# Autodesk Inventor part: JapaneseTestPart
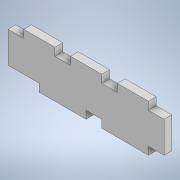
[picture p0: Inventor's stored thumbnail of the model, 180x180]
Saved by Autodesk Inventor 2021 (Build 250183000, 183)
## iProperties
Created: 2026-10
Part Number: JapaneseTestPart
Material: Generic
Document SubType Name: Modeling
Designer: hp
Density: 1 g/cm^3
Appearance: Default
Author: hp
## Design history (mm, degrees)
sketch "Sketch1" dims "d15" = 10
  geometry: L1 (0, 0)-(100, 0); L2 (100, 0)-(100, 20); L3 (100, 20)-(0, 20); L4 (0, 20)-(0, 0); L5 (90, -5)-(90, 0); L6 (90, 0)-(60, 0); L7 (60, 0)-(60, -5); L8 (60, -5)-(90, -5); L9 (50, -5)-(50, 0); L10 (20, 0)-(20, -5); L11 (20, -5)-(50, -5); L12 (50, 0)-(20, 0); L13 (60, 20)-(60, 25); L14 (70, 25)-(70, 20); L15 (70, 20)-(90, 20); L16 (90, 25)-(70, 25); L17 (90, 20)-(90, 25); L18 (30, 20)-(30, 25); L19 (30, 25)-(10, 25); L20 (10, 20)-(30, 20); L21 (10, 25)-(10, 20); L22 (40, 20)-(60, 20); L23 (60, 25)-(40, 25); L24 (40, 25)-(40, 20); 12 further points
  constraints: 48 end point, 8 parallel, 5 horizontal, 4 perpendicular, 2 collinear, 2 midpoint, 2 point on line, 15 other
  dimensions: "d0" = 100 distance of L3.end L2.end; "d1" = 20 distance of L1.end L2.end; "d2" = 30 distance of L5.start L7.end; "d3" = 5 distance of L7.end L6.end; "d4" = 30 distance of L9.start L10.end; "d5" = 5 distance of L10.end L10.start; "d6" = 10 distance between parallel lines of L9 L7; "d7" = 10 distance from line of L5 L1.end; "d12" = 20 distance of L15.end L14.end; "d13" = 5 distance of L14.end L14.start; "d14" = 30 distance of L14.end L22.start; "d16" = 10 distance from line of L2.end L17
extrude "Extrusion1" new body sketch "Sketch1" distance "d17" = 5; taper "d18" = 0 deg
body "Solid1"
